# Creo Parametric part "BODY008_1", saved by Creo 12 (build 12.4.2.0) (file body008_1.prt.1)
Units: Custom; MM, KILOGRAM, SECS

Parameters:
  PTC_WM_ITERATION = "0"
  PTC_WM_VERSION = "-.0"
  PTC_WM_LIFECYCLE_STATE = "In Work"
  PTC_WM_LIFECYCLE = "MO_CADDocument"
  PTC_WM_CREATED_BY = "Maximilian Roepper (Z0017RMS: MO)"
  PTC_WM_CREATED_ON = "18-Sep-26 11:36:42 AM"
  PTC_WM_MODIFIED_BY = "Maximilian Roepper (Z0017RMS: MO)"
  PTC_WM_MODIFIED_ON = "18-Sep-26 11:36:46 AM"
  PDMLINKNUMBER = "PDM000071455175"
  PTC_WM_NAME = "body008_1.prt"
  PTC_WM_NUMBER = "PDM000071455175"

Other parameters: WEIGHT, WEIGHT_FACTOR, WEIGHT_ADD, _MASS_TEMP, _DIFF_TEMP, MC_ERRORS, SUPPLIER

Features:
  1. coordinate system
  2. datum plane "PRT_YZ"
  3. datum plane "PRT_XY"
  4. datum plane "PRT_XZ"
  5. coordinate system
  6. datum axis
  7. datum axis
  8. datum axis
  9. coordinate system
  10. imported feature

Other named items: PRT, SIEMENS_MO, DRW_VIEW_ORG, PRT_X, PRT_Y, PRT_Z, CS0, ROUGH_GROB

Layers: 00_STD_CSYS-KSYS, 01_STD_PLANES-EBENEN, 02_STD_AXES-ACHSEN, 03_STD_CSYS-KSYS, 24_IMPORT_FEAT-IMPORT_KE

Surfaces: 6 plane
